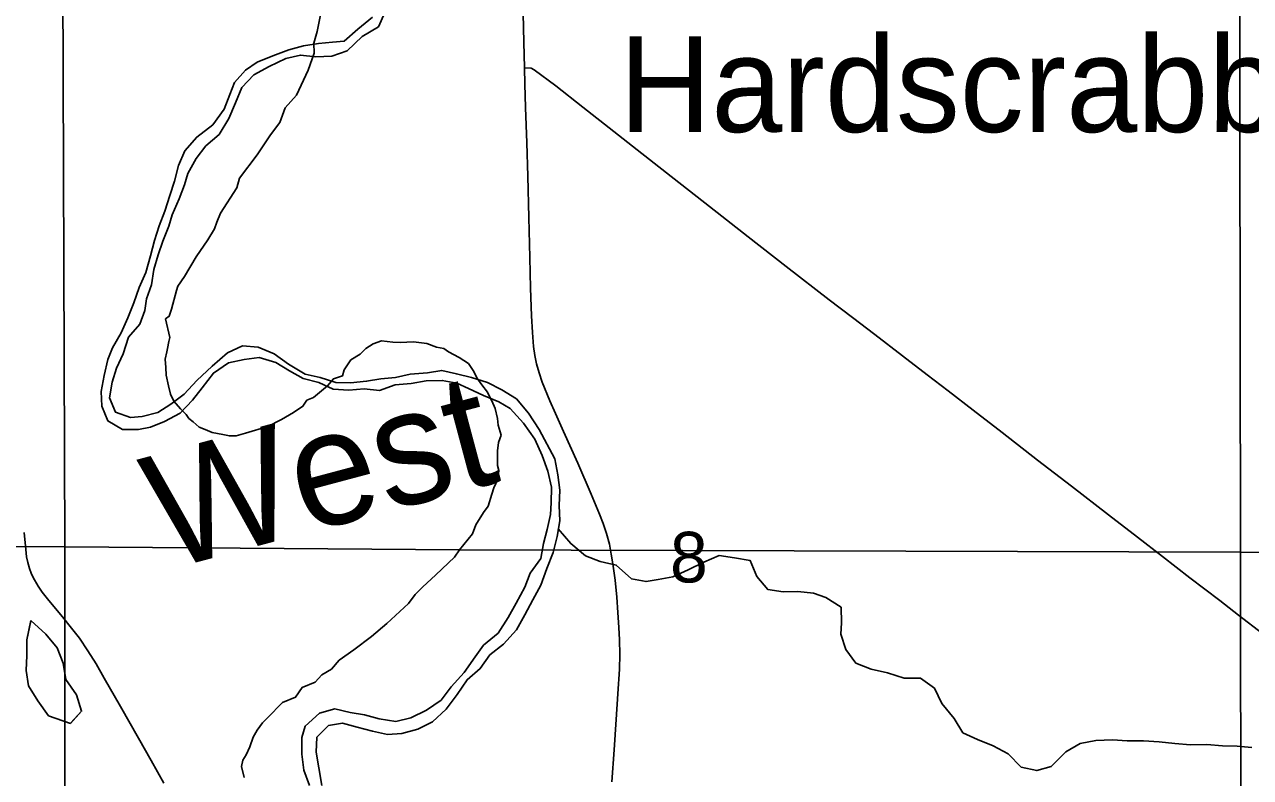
# Model space of a CAD drawing. Extents: x 0 to 34, y 0 to 22.
# Drawn here: x 2.784 to 3.29, y 19.545 to 19.857 of the extents above; entities that cross this region are included whole.
import ezdxf

# ---------------------------------------------------------------- set-up
doc = ezdxf.new("R2010")
doc.units = 0
for name, color, linetype in [('GM_X_County_Road', 7, 'Continuous'), ('GM_X_Major_River', 7, 'Continuous'), ('GM_X_Major_River_Text', 7, 'Continuous'), ('GM_X_Minor_Lake', 7, 'Continuous'), ('GM_X_Minor_River', 7, 'Continuous'), ('GM_X_Section', 7, 'Continuous'), ('GM_X_Section_Text', 7, 'Continuous'), ('GM_X_State_Route', 7, 'Continuous'), ('GM_X_Township_Road', 7, 'Continuous'), ('GM_X_Unincorporated_Text', 7, 'Continuous')]:
    doc.layers.add(name, color=color, linetype=linetype)

msp = doc.modelspace()

# ---------------------------------------------------------------- linework, layer by layer
at = {"layer": 'GM_X_County_Road'}
msp.add_lwpolyline([(2.99034, 19.83883), (2.993, 19.83865), (2.99435, 19.83799), (3.00327, 19.83133), (3.01447, 19.82247), (3.02718, 19.81246), (3.03494, 19.80637), (3.051, 19.7939), (3.0649, 19.78298), (3.08284, 19.76889), (3.09854, 19.75666), (3.11631, 19.74292), (3.12597, 19.73554), (3.13514, 19.7286), (3.14663, 19.71981), (3.15679, 19.71192), (3.16554, 19.70524), (3.17589, 19.69734), (3.18779, 19.68802), (3.2025, 19.6766), (3.21643, 19.66584), (3.23178, 19.65398), (3.24377, 19.64475), (3.25415, 19.63674), (3.26544, 19.62803), (3.27785, 19.61854), (3.28558, 19.61256), (3.29556, 19.60487)], dxfattribs=at)
at = {"layer": 'GM_X_Major_River'}
for points in [[(3.00214, 19.63845), (3.00381, 19.6451), (3.00492, 19.65156), (3.0047, 19.65783), (3.00486, 19.66428), (3.00407, 19.67055), (3.0029, 19.67718), (2.99639, 19.6893), (2.992, 19.69611), (2.98704, 19.70197), (2.98096, 19.70573), (2.97506, 19.70873), (2.96842, 19.71078), (2.96215, 19.71227), (2.95608, 19.71375), (2.95021, 19.71277), (2.94301, 19.71216), (2.93695, 19.71079), (2.93089, 19.71019), (2.92501, 19.70921), (2.91838, 19.7086), (2.91231, 19.70876), (2.90586, 19.71081), (2.8996, 19.7121), (2.89275, 19.71624), (2.88685, 19.72057), (2.88021, 19.72338), (2.87376, 19.72391), (2.86752, 19.72103), (2.8611, 19.71549), (2.85487, 19.70957), (2.84959, 19.70384), (2.84411, 19.69982), (2.83863, 19.69637), (2.8322, 19.69463), (2.82746, 19.69422), (2.82119, 19.69646), (2.8187, 19.70234), (2.8198, 19.7088), (2.82167, 19.71469), (2.8243, 19.72059), (2.82654, 19.72744), (2.83125, 19.73278), (2.83331, 19.73849), (2.83404, 19.74324), (2.8361, 19.74914), (2.83702, 19.75541), (2.83888, 19.7615), (2.84075, 19.7672), (2.84319, 19.77329), (2.84468, 19.77805), (2.84749, 19.78471), (2.84974, 19.79042), (2.85104, 19.79517), (2.85461, 19.80127), (2.85857, 19.80661), (2.86404, 19.81119), (2.86799, 19.81786), (2.8708, 19.82433), (2.87342, 19.83061), (2.87833, 19.83596), (2.88476, 19.83941), (2.89156, 19.84268), (2.89762, 19.84404), (2.90407, 19.84332), (2.91071, 19.84355), (2.91695, 19.84586), (2.92318, 19.85178), (2.92998, 19.85581), (2.93261, 19.86171)], [(2.9275, 19.85978), (2.92146, 19.85481), (2.9158, 19.84984), (2.91087, 19.84943), (2.90518, 19.84883), (2.89893, 19.84785), (2.89287, 19.84629), (2.88625, 19.84379), (2.87982, 19.84109), (2.87491, 19.83784), (2.87038, 19.83269), (2.86851, 19.82774), (2.86608, 19.82165), (2.86137, 19.81517), (2.85476, 19.81019), (2.84986, 19.80447), (2.84723, 19.79838), (2.84556, 19.79191), (2.84369, 19.78602), (2.84164, 19.77955), (2.8392, 19.77346), (2.83734, 19.76737), (2.83566, 19.7611), (2.8338, 19.75425), (2.83099, 19.74797), (2.82874, 19.74169), (2.82631, 19.73541), (2.82349, 19.72932), (2.81992, 19.72304), (2.81805, 19.71828), (2.81657, 19.71163), (2.81527, 19.70497), (2.81549, 19.6989), (2.81799, 19.69284), (2.82407, 19.68927), (2.83071, 19.6893), (2.83563, 19.69028), (2.84149, 19.69259), (2.84792, 19.69605), (2.85301, 19.70139), (2.85697, 19.70654), (2.86168, 19.71264), (2.86792, 19.71686), (2.87435, 19.71822), (2.88061, 19.71902), (2.88744, 19.71697), (2.89314, 19.71358), (2.89885, 19.71039), (2.9053, 19.70872), (2.91119, 19.7059), (2.91764, 19.70556), (2.92408, 19.70616), (2.93034, 19.70544), (2.93677, 19.70776), (2.94341, 19.70836), (2.94966, 19.70935), (2.95629, 19.70958), (2.96236, 19.70847), (2.96711, 19.70622), (2.97338, 19.70341), (2.97965, 19.70078), (2.98441, 19.69796), (2.98993, 19.69192), (2.99452, 19.6853), (2.99758, 19.67848), (2.99989, 19.67204), (3.00144, 19.6654), (3.00128, 19.65895), (3.00111, 19.6542), (2.99963, 19.64793), (2.99814, 19.64222), (2.99703, 19.63595), (2.9927, 19.62985), (2.99045, 19.62414)], [(2.90652, 19.54213), (2.90532, 19.54942), (2.90415, 19.55587), (2.9045, 19.56214), (2.90922, 19.56691), (2.91509, 19.56789), (2.92117, 19.56622), (2.92743, 19.56455), (2.93369, 19.56325), (2.93957, 19.56367), (2.94619, 19.56541), (2.95224, 19.56849), (2.95791, 19.57364), (2.96243, 19.57975), (2.96657, 19.58584), (2.97204, 19.59043), (2.97599, 19.59615), (2.98166, 19.60055), (2.98694, 19.60646), (2.99051, 19.61275), (2.9937, 19.61884), (2.99709, 19.62494), (2.99952, 19.63179), (3.00214, 19.63845)], [(2.99045, 19.62414), (2.98689, 19.61748), (2.9835, 19.61157), (2.97936, 19.60509), (2.97332, 19.60012), (2.96993, 19.59536), (2.96541, 19.58887), (2.95995, 19.58296), (2.9558, 19.57743), (2.94976, 19.57322), (2.94333, 19.57014), (2.93708, 19.56859), (2.93025, 19.56969), (2.92417, 19.57136), (2.91829, 19.57228), (2.91184, 19.57376), (2.90559, 19.57202), (2.89955, 19.56667), (2.89825, 19.56191), (2.89828, 19.55508), (2.89907, 19.54844), (2.90138, 19.54219)]]:
    msp.add_lwpolyline(points, dxfattribs=at)
at = {"layer": 'GM_X_Minor_Lake'}
for points in [[(2.78621, 19.61036), (2.78455, 19.60237), (2.78456, 19.59592), (2.78419, 19.58965), (2.78515, 19.58339), (2.78914, 19.57713), (2.79351, 19.57087), (2.80254, 19.56777)], [(2.78617, 19.61014), (2.78455, 19.60237), (2.78456, 19.59592), (2.78419, 19.58965), (2.78515, 19.58339), (2.78914, 19.57713), (2.79351, 19.57087), (2.80253, 19.56777)], [(2.80254, 19.56777), (2.80717, 19.57281), (2.80507, 19.57964), (2.8007, 19.5859), (2.79955, 19.59273), (2.79707, 19.59899), (2.79232, 19.60468), (2.78621, 19.61036)], [(2.80262, 19.56786), (2.80717, 19.57281), (2.80507, 19.57964), (2.8007, 19.5859), (2.79955, 19.59273), (2.79707, 19.59899), (2.79232, 19.60468), (2.78625, 19.61032)]]:
    msp.add_lwpolyline(points, dxfattribs=at)
at = {"layer": 'GM_X_Minor_River'}
msp.add_lwpolyline([(3.00428, 19.6482), (3.00946, 19.64213), (3.01554, 19.63702), (3.02161, 19.63475), (3.02826, 19.63325), (3.03452, 19.62757), (3.04059, 19.62645), (3.04553, 19.62722), (3.05159, 19.62838), (3.05804, 19.63125), (3.06448, 19.63449), (3.07074, 19.63717), (3.07719, 19.63624), (3.08364, 19.63511), (3.08631, 19.62848), (3.09087, 19.62317), (3.09732, 19.62224), (3.10339, 19.62226), (3.10984, 19.6217), (3.11496, 19.61982), (3.12123, 19.61585), (3.12143, 19.60939), (3.12106, 19.60464), (3.12315, 19.59838), (3.12733, 19.5927), (3.1336, 19.59024), (3.14043, 19.58874), (3.14726, 19.58648), (3.15409, 19.5865), (3.15979, 19.58234), (3.16283, 19.57608), (3.16796, 19.56983), (3.17157, 19.56395), (3.17765, 19.56112), (3.1841, 19.55848), (3.19037, 19.55527), (3.19569, 19.54977), (3.20214, 19.54827), (3.20802, 19.55), (3.21408, 19.55609), (3.22014, 19.55953), (3.22659, 19.56068), (3.23342, 19.56108), (3.23949, 19.56053), (3.24632, 19.56055), (3.25277, 19.56018), (3.25922, 19.55944), (3.26567, 19.55889), (3.2725, 19.5591), (3.27895, 19.55855), (3.28502, 19.55837), (3.29109, 19.55782)], dxfattribs=at)
at = {"layer": 'GM_X_Section'}
for points in [[(2.55738, 19.90968), (2.72126, 19.90689), (2.74749, 19.89512), (2.7871, 19.91018), (2.79928, 19.91335), (2.80028, 19.64085), (2.56001, 19.64218)], [(3.53172, 19.90795), (3.53581, 19.63725), (3.28633, 19.63857), (3.28602, 19.9078)], [(2.56001, 19.64218), (2.80028, 19.64085), (2.80042, 19.37489), (2.56365, 19.3759)], [(3.53581, 19.63725), (3.53702, 19.37026), (3.28663, 19.37379), (3.28633, 19.63857)]]:
    msp.add_lwpolyline(points, close=True, dxfattribs=at)
for points in [[(2.90939, 19.8782), (2.90453, 19.85381), (2.90327, 19.84895), (2.9033, 19.84487), (2.9009, 19.83784), (2.89605, 19.82749), (2.89129, 19.82225), (2.88913, 19.81625), (2.88528, 19.81114), (2.87977, 19.80283), (2.87245, 19.79325), (2.87131, 19.78916), (2.86465, 19.77868), (2.86312, 19.77498), (2.8621, 19.77229), (2.85942, 19.76769), (2.85454, 19.76067), (2.84968, 19.75249), (2.84698, 19.74853), (2.84648, 19.74674), (2.84434, 19.73908), (2.84345, 19.73614), (2.8419, 19.73499), (2.84365, 19.72733), (2.84328, 19.72567), (2.84265, 19.72273), (2.84241, 19.72133), (2.84178, 19.71839), (2.84194, 19.71494), (2.8421, 19.71175), (2.84317, 19.70741), (2.84398, 19.70396), (2.8453, 19.70103), (2.84805, 19.69784), (2.85041, 19.69555), (2.85146, 19.69389), (2.85329, 19.69249), (2.85577, 19.69032), (2.85825, 19.6893), (2.86112, 19.68803), (2.86554, 19.68727), (2.86827, 19.68663), (2.87112, 19.68664), (2.87488, 19.68779), (2.8842, 19.69049), (2.88989, 19.69343), (2.8948, 19.69637), (2.89867, 19.69893), (2.90034, 19.70136), (2.90306, 19.70251), (2.90886, 19.70737), (2.9113, 19.71018), (2.91506, 19.71147), (2.91568, 19.71402), (2.91851, 19.71811), (2.92238, 19.72041), (2.9247, 19.72271), (2.9278, 19.72476), (2.93116, 19.72591), (2.93584, 19.72541), (2.93896, 19.72529), (2.94441, 19.72555), (2.94987, 19.72479), (2.9539, 19.72326), (2.95702, 19.72276), (2.95885, 19.72135), (2.96329, 19.71906), (2.9672, 19.71651), (2.96931, 19.71333), (2.97063, 19.71065), (2.97273, 19.70771), (2.97496, 19.70478), (2.97615, 19.70235), (2.97681, 19.70108), (2.97813, 19.69802), (2.9792, 19.6938), (2.97949, 19.69112), (2.98069, 19.68691), (2.97954, 19.68397), (2.97918, 19.68053), (2.97921, 19.67797), (2.97911, 19.6744), (2.97964, 19.67236), (2.97928, 19.66878), (2.97762, 19.6652), (2.97687, 19.66252), (2.97535, 19.65767), (2.97342, 19.65498), (2.97022, 19.64987), (2.96882, 19.64617), (2.96344, 19.63954), (2.80028, 19.64085), (2.79928, 19.91335)], [(3.28602, 19.9078), (3.28633, 19.63857), (2.96344, 19.63954), (2.96882, 19.64617), (2.97022, 19.64987), (2.97342, 19.65498), (2.97535, 19.65767), (2.97687, 19.66252), (2.97762, 19.6652), (2.97928, 19.66878), (2.97964, 19.67236), (2.97911, 19.6744), (2.97921, 19.67797), (2.97918, 19.68053), (2.97954, 19.68397), (2.98069, 19.68691), (2.97949, 19.69112), (2.9792, 19.6938), (2.97813, 19.69802), (2.97681, 19.70108), (2.97615, 19.70235), (2.97496, 19.70478), (2.97273, 19.70771), (2.97063, 19.71065), (2.96931, 19.71333), (2.9672, 19.71651), (2.96329, 19.71906), (2.95885, 19.72135), (2.95702, 19.72276), (2.9539, 19.72326), (2.94987, 19.72479), (2.94441, 19.72555), (2.93896, 19.72529), (2.93584, 19.72541), (2.93116, 19.72591), (2.9278, 19.72476), (2.9247, 19.72271), (2.92238, 19.72041), (2.91851, 19.71811), (2.91568, 19.71402), (2.91506, 19.71147), (2.9113, 19.71018), (2.90886, 19.70737), (2.90306, 19.70251), (2.90034, 19.70136), (2.89867, 19.69893), (2.8948, 19.69637), (2.88989, 19.69343), (2.8842, 19.69049), (2.87488, 19.68779), (2.87112, 19.68664), (2.86827, 19.68663), (2.86554, 19.68727), (2.86112, 19.68803), (2.85825, 19.6893), (2.85577, 19.69032), (2.85329, 19.69249), (2.85146, 19.69389), (2.85041, 19.69555), (2.84805, 19.69784), (2.8453, 19.70103), (2.84398, 19.70396), (2.84317, 19.70741), (2.8421, 19.71175), (2.84194, 19.71494), (2.84178, 19.71839), (2.84241, 19.72133), (2.84265, 19.72273), (2.84328, 19.72567), (2.84365, 19.72733), (2.8419, 19.73499), (2.84345, 19.73614), (2.84434, 19.73908), (2.84648, 19.74674), (2.84698, 19.74853), (2.84968, 19.75249), (2.85454, 19.76067), (2.85942, 19.76769), (2.8621, 19.77229), (2.86312, 19.77498), (2.86465, 19.77868), (2.87131, 19.78916), (2.87245, 19.79325), (2.87977, 19.80283), (2.88528, 19.81114), (2.88913, 19.81625), (2.89129, 19.82225), (2.89605, 19.82749), (2.9009, 19.83784), (2.9033, 19.84487), (2.90327, 19.84895), (2.90453, 19.85381), (2.90939, 19.8782)], [(2.80042, 19.37489), (2.80028, 19.64085), (2.96344, 19.63954), (2.96138, 19.63646), (2.95365, 19.62917), (2.94811, 19.62418), (2.94515, 19.62111), (2.94232, 19.61741), (2.93343, 19.6091), (2.92698, 19.60372), (2.91976, 19.59822), (2.91369, 19.594), (2.91048, 19.59017), (2.90648, 19.58787), (2.90377, 19.5848), (2.89834, 19.58262), (2.89565, 19.57866), (2.89021, 19.57648), (2.88918, 19.57533), (2.88519, 19.57124), (2.88197, 19.56804), (2.87979, 19.56498), (2.87813, 19.56216), (2.87673, 19.55808), (2.8752, 19.55476), (2.87379, 19.55258), (2.8733, 19.55003), (2.87437, 19.54543)], [(2.87437, 19.54543), (2.8733, 19.55003), (2.87379, 19.55258), (2.8752, 19.55476), (2.87673, 19.55808), (2.87813, 19.56216), (2.87979, 19.56498), (2.88197, 19.56804), (2.88519, 19.57124), (2.88918, 19.57533), (2.89021, 19.57648), (2.89565, 19.57866), (2.89834, 19.58262), (2.90377, 19.5848), (2.90648, 19.58787), (2.91048, 19.59017), (2.91369, 19.594), (2.91976, 19.59822), (2.92698, 19.60372), (2.93343, 19.6091), (2.94232, 19.61741), (2.94515, 19.62111), (2.94811, 19.62418), (2.95365, 19.62917), (2.96138, 19.63646), (2.96344, 19.63954), (3.28633, 19.63857), (3.28663, 19.37379)]]:
    msp.add_lwpolyline(points, dxfattribs=at)
at = {"layer": 'GM_X_State_Route'}
msp.add_lwpolyline([(3.02647, 19.54367), (3.02737, 19.55686), (3.02818, 19.56947), (3.02891, 19.58004), (3.02961, 19.59019), (3.02974, 19.59631), (3.0296, 19.60231), (3.02931, 19.60749), (3.02892, 19.61361), (3.02847, 19.61998), (3.02784, 19.627), (3.02686, 19.63379), (3.02621, 19.63778), (3.02539, 19.64189), (3.02415, 19.64637), (3.02288, 19.65039), (3.02136, 19.65434), (3.0179, 19.66258), (3.01231, 19.67538), (3.00642, 19.68842), (3.00307, 19.69589), (3.00081, 19.70111), (2.99767, 19.70892), (2.99641, 19.71275), (2.99534, 19.71649), (2.9946, 19.71982), (2.99406, 19.72366), (2.99355, 19.72945), (2.99317, 19.73633), (2.99284, 19.74774), (2.99252, 19.76046), (2.9921, 19.77699), (2.99165, 19.79404), (2.99122, 19.80785), (2.99074, 19.82236), (2.99045, 19.83202), (2.99034, 19.83883), (2.99001, 19.84937), (2.98975, 19.86124)], dxfattribs=at)
at = {"layer": 'GM_X_Township_Road'}
msp.add_lwpolyline([(2.84123, 19.54311), (2.83591, 19.55244), (2.83064, 19.5617), (2.8232, 19.57482), (2.81657, 19.58644), (2.81321, 19.59239), (2.80976, 19.59784), (2.80626, 19.60301), (2.80249, 19.60782), (2.79986, 19.61118), (2.7931, 19.61926), (2.79093, 19.62202), (2.78928, 19.62449), (2.78715, 19.62816), (2.78626, 19.62996), (2.78565, 19.63179), (2.78488, 19.63429), (2.78438, 19.63666), (2.78405, 19.63974), (2.78337, 19.64672)], dxfattribs=at)

# ---------------------------------------------------------------- texts
at = {"layer": 'GM_X_Major_River_Text'}
msp.add_text('West', height=0.047372, rotation=14.9226, dxfattribs=at).set_placement((2.84172, 19.63092))
at = {"layer": 'GM_X_Section_Text'}
msp.add_text('8', height=0.02093, rotation=0, dxfattribs=at).set_placement((3.0505, 19.62607))
at = {"layer": 'GM_X_Unincorporated_Text'}
msp.add_text('Hardscrabble', height=0.0394886, rotation=0, dxfattribs=at).set_placement((3.02945, 19.81227))

doc.saveas('drawing.dxf')
